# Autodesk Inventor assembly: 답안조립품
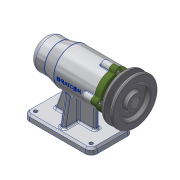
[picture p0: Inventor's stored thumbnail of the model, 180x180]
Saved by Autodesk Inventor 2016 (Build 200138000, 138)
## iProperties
Created: 2019-07
Part Number: 답안조립품
Material: 일반
Document SubType Name: Assembly
Designer: 605-11
Author: 605-11
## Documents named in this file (12)
- C:\Users\605-11\Desktop\490704V1065\답안조립품.iam
- C:\Users\605-11\Desktop\490704V1065\1.본체.ipt
- C:\Users\605-11\Desktop\490704V1065\베어링 6004.ipt
- C:\Users\605-11\Desktop\490704V1065\축.ipt
- C:\Users\605-11\Desktop\490704V1065\베어링 51202.ipt
- C:\Users\605-11\Desktop\490704V1065\어댑터슬리브.ipt
- C:\Users\605-11\Desktop\490704V1065\볼트 M4.ipt
- C:\Users\605-11\Desktop\490704V1065\커버.ipt
- C:\Users\605-11\Desktop\490704V1065\오일 실.ipt
- C:\Users\605-11\Desktop\490704V1065\키 5 x 5 x 16.ipt
- C:\Users\605-11\Desktop\490704V1065\V벨트풀리.ipt
- C:\Users\605-11\Desktop\490704V1065\멈춤나사 M3.ipt
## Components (2 placed, 2 different names)
1. 1.본체:1
2. V벨트풀리:1
